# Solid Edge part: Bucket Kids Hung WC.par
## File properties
Title: Bucket Kids Hung WC
Author: DESYS
Template: Parte SCARABEO.par
Last saved by: i.fialdini
Revision: 55
Application: Solid Edge
Stile della faccia: Model Default
Coef. of Thermal Exp: 0.0
Thermal Conductivity: 0.0
Specific Heat: 0.0
Modulus of Elasticity: 0.0
Poisson's Ratio: 0.0
Yield Stress: 0.0
Ultimate Stress: 0.0
Elongation: 0.0
Tipo di contenuto documento: 0
Precisione: 0.990
Document Number: 8815
Revision: 0
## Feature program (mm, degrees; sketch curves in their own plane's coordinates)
lofted protrusion "unnamed LoftedProtrusion 1"
sketch for "unnamed Protrusion 1" plane through (-217.5, 0, -220) normal (-1, 0, 0) x-axis (0, -1, 0)
extrude "unnamed Protrusion 1" add through along -normal
fillet "unnamed Round 1"
fillet "Rotondo_24" radius 200
sketch for "ScavoEstrusione_3" plane through (-17.4962, 0.1233, 0) normal (0, 0, 1) x-axis (0, -1, 0)
extrude "ScavoEstrusione_3" cut finite 135 along -normal
sketch for "unnamed Cutout 1" #1 plane through (0, 0, -135) normal (0, 0, 1) x-axis (-1, 0, 0)
  arc centre (-16.5, 0) radius 100 from (-16.5, -100) to (-16.5, 100) ccw
  line (-16.5, 100) -> (-46.5, 100)
  arc centre (-46.5, 0) radius 100 from (-46.5, 100) to (-46.5, -100) ccw
  line (-46.5, -100) -> (-16.5, -100)
sketch for "unnamed Cutout 1" #2 plane through (0, 0, -135) normal (0, 0, 1) x-axis (-1, 0, 0)
  arc centre (-16.5, 0) radius 115 from (-16.5, -115) to (-16.5, 115) ccw
  line (-16.5, 115) -> (-46.5, 115)
  arc centre (-46.5, 0) radius 115 from (-46.5, 115) to (-46.5, -115) ccw
  line (-46.5, -115) -> (-16.5, -115)
extrude "unnamed Cutout 1" cut finite 70 along +normal
sketch for "unnamed Cutout 2" #1 plane through (20.5, 0, -65) normal (0, 0, 1) x-axis (1, 0, 0)
  arc centre (-4, 0) radius 115 from (-4, 115) to (-4, -115) ccw
  line (-4, -115) -> (26, -115)
  arc centre (26, 0) radius 115 from (26, -115) to (26, 115) ccw
  line (26, 115) -> (-4, 115)
sketch for "unnamed Cutout 2" #2 plane through (20.5, 0, -65) normal (0, 0, 1) x-axis (1, 0, 0)
  arc centre (-4, 0) radius 105 from (-4, 105) to (-4, -105) ccw
  line (-4, -105) -> (26, -105)
  arc centre (26, 0) radius 105 from (26, -105) to (26, 105) ccw
  line (26, 105) -> (-4, 105)
extrude "unnamed Cutout 2" cut finite 50 along +normal
sketch used by "ScavoEstrusione_6" plane through (-36.4973, -0.0393, -225) normal (0, 0, -1) x-axis (0, 1, 0)
extrude "ScavoEstrusione_6" cut finite 87 along -normal
sketch used by "ProtrusioneEstrusa_9" plane through (-36.4973, -0.0393, -225) normal (0, 0, -1) x-axis (-1, 0, 0)
  line (-158.0515, 10.8084) -> (-169.1638, 20.0393)
  line (-158.0515, -10.7298) -> (-169.1638, -19.9607)
extrude "ProtrusioneEstrusa_9" add through along -normal  Treatment1_DraftAngle = 3.5 deg
sketch for "unnamed Cutout 3" plane through (-36.4973, -0.0393, -225) normal (0, 0, -1) x-axis (1, 0, 0)
extrude "unnamed Cutout 3" cut to key point along -normal
sketch for "ScavoEstrusione_8" plane through (-36.4973, -0.0393, -225) normal (0, 0, -1) x-axis (1, 0, 0)
extrude "ScavoEstrusione_8" cut finite 261.6824 symmetric
mirror "unnamed Mirror 1" of "ScavoEstrusione_8" about plane through (0, 0, 0) normal (0, -1, 0)
extrude "unnamed Cutout 4" cut finite 261.6824 symmetric
sketch for "ProtrusioneEstrusa_10" plane through (-217.5, 0, -110) normal (-1, 0, 0) x-axis (0, 1, 0)
  line (-90.5, 115) -> (90.5, 115)
extrude "ProtrusioneEstrusa_10" add finite 40 along -normal
sketch for "unnamed RevolvedProtrusion 1" plane through (0, 0, 0) normal (1, 0, 0) x-axis (0, 1, 0)
  arc centre (0, -40.7154) radius 146.8479 from (-110, -138) to (0, -187.5633) ccw
revolve "unnamed RevolvedProtrusion 1" add full turn 360 deg about sketch line (0, 0) -> (0, -253.8574)
sketch for "ScavoEstrusione_10" plane through (-217.5, 0, -140) normal (-1, 0, 0) x-axis (0, 1, 0)
extrude "ScavoEstrusione_10" cut finite 80 along -normal
fillet "Rotondo_34" radius 25
fillet "Rotondo_35" radius 25
fillet "Rotondo_36" radius 10
fillet "Rotondo_37" radius 5
fillet "Rotondo_38" radius 1
fillet "Rotondo_40" radius 1
fillet "Rotondo_41" radius 2
fillet "Rotondo_42" radius 4
fillet "Rotondo_44" radius 10
fillet "Rotondo_46" radius 1
fillet "Rotondo_47" radius 5  Radii2 = 4 mm
delete blends "unnamed DeleteBlends 1"
delete faces "unnamed DeleteFaces 1"
sketch for "ScavoRivoluzione_1" plane through (0, 0, 0) normal (0, -1, 0) x-axis (1, 0, 0)
  line (-178.5, -138) -> (-110, -138)
  arc centre (0, -40.7154) radius 146.8479 from (-121.6287, -123) to (-110, -138) ccw
  line (-121.6287, -123) -> (-217.5, -123)
revolve "ScavoRivoluzione_1" cut finite 29 deg about sketch line (0, -40.7154) -> (0, -174.5688)
replace surface "unnamed ReplaceSurface 1"
replace surface "unnamed ReplaceSurface 2"
sketch for "ProtrusioneEstrusa_11" plane through (-24.0203, 0, -138) normal (0, 0, -1) x-axis (0, 1, 0)
extrude "ProtrusioneEstrusa_11" add finite 150 along +normal  Treatment1_DraftAngle = 2.5 deg
draft "unnamed Draft 1"
fillet "Rotondo_29" radius 58.5
sketch for "ProtrusioneEstrusa_12" plane through (-183.5, 0, -140) normal (-1, 0, 0) x-axis (0, 1, 0)
  circle centre (0, 45) radius 47
extrude "ProtrusioneEstrusa_12" add through along -normal  Treatment1_DraftAngle = 3 deg
sketch for "ScavoEstrusione_12" plane through (0, 0, 0) normal (0, -1, 0) x-axis (1, 0, 0)
  line (-140.2746, -217.0534) -> (-129.0341, -190.5)
  line (-129.0341, -190.5) -> (-73.4248, -190.5)
  line (-73.4248, -190.5) -> (-72.2654, -217.0534)
  line (-72.2654, -217.0534) -> (-140.2746, -217.0534)
extrude "ScavoEstrusione_12" cut finite 139.0806 symmetric
sketch for "unnamed Cutout 5" #1 plane through (-217.5, 0, -140) normal (-1, 0, 0) x-axis (0, -1, 0)
  circle centre (-91, 60) radius 14
  dimension (linear) = 91
  dimension (linear) = 91
sketch for "unnamed Cutout 5" #2 plane through (-217.5, 0, -140) normal (-1, 0, 0) x-axis (0, -1, 0)
  circle centre (91, 60) radius 14
extrude "unnamed Cutout 5" cut finite 40 along -normal
sketch for "ScavoEstrusione_14" #1 plane through (-217.5, 0, -140) normal (-1, 0, 0) x-axis (0, -1, 0)
  circle centre (-47.5, 126) radius 4
sketch for "ScavoEstrusione_14" #2 plane through (-217.5, 0, -140) normal (-1, 0, 0) x-axis (0, -1, 0)
  circle centre (-100.5, 126) radius 5
sketch for "ScavoEstrusione_14" #3 plane through (-217.5, 0, -140) normal (-1, 0, 0) x-axis (0, -1, 0)
  circle centre (100.5, 126) radius 5
sketch for "ScavoEstrusione_14" #4 plane through (-217.5, 0, -140) normal (-1, 0, 0) x-axis (0, -1, 0)
  circle centre (47.5, 126) radius 4
extrude "ScavoEstrusione_14" cut finite 75.5672 along -normal
sketch for "unnamed Cutout 6" plane through (-217.5, 0, -140) normal (-1, 0, 0) x-axis (0, -1, 0)
  circle centre (0, 95) radius 24
extrude "unnamed Cutout 6" cut through along -normal
sketch for "ScavoEstrusione_16" plane through (-217.5, 0, -140) normal (-1, 0, 0) x-axis (0, -1, 0)
  circle centre (0, 95) radius 27.5
extrude "ScavoEstrusione_16" cut finite 38 along -normal
sketch for "ScavoEstrusione_17" plane through (-217.5, 0, -140) normal (-1, 0, 0) x-axis (0, -1, 0)
  line (-107.5, 78.7816) -> (-107.5, 113.3583)
  line (-107.5, 41.2184) -> (-107.5, -52)
  line (-107.5, -52) -> (-95.5683, -52)
  arc centre (0, -40.7748) radius 96.2252 from (-95.5683, -52) to (95.5683, -52) ccw
  line (107.5, -52) -> (95.5683, -52)
  line (107.5, 41.2184) -> (107.5, -52)
  arc centre (91, 60) radius 25 from (107.5, 78.7816) to (107.5, 41.2184) ccw
  line (107.5, 78.7816) -> (107.5, 118.2601)
  arc centre (99.6624, 131.0496) radius 15 from (84.8031, 129) to (107.5, 118.2601) ccw
  line (62.1969, 129) -> (84.8031, 129)
  arc centre (47.5, 126) radius 15 from (34.1398, 119.1805) to (62.1969, 129) ccw
  arc centre (25.233, 114.6342) radius 10 from (34.1398, 119.1805) to (29.302, 123.7689) ccw
  arc centre (0, 57.9871) radius 72.0129 from (-29.302, 123.7689) to (29.302, 123.7689) cw
  arc centre (-25.233, 114.6342) radius 10 from (-29.302, 123.7689) to (-34.1398, 119.1805) ccw
  line (-84.8031, 129) -> (-62.1969, 129)
extrude "ScavoEstrusione_17" cut finite 4 along -normal
sketch for "unnamed Cutout 7" plane through (-13.6958, 0, -260.9151) normal (0, 0, 1) x-axis (1, 0, 0)
  line (-53.8042, 10.982) -> (-53.8042, 38.9877)
  line (-53.8042, 38.9877) -> (-65.552, 38.9877)
  arc centre (-32.7479, 0) radius 50.9524 from (-65.552, 38.9877) to (-77.925, 23.5624) ccw
  line (-53.8042, 10.982) -> (-77.925, 23.5624)
extrude "unnamed Cutout 7" cut to key point along +normal
extrude "unnamed Cutout 8" cut finite 68.9151
sketch for "ProtrusioneEstrusa_15" plane through (-67.5, 0, -163.5) normal (1, 0, 0) x-axis (0, 1, 0)
  line (-36.0423, -43.5) -> (35.0423, -43.5)
  line (35.0423, -43.5) -> (36.0423, -43.5)
  line (36.0423, -43.5) -> (36.0423, -28.4999)
  arc centre (0, -28.5) radius 36.0423 from (36.0423, -28.4999) to (-36.0423, -28.5) ccw
  line (-36.0423, -28.5) -> (-36.0423, -43.5)
extrude "ProtrusioneEstrusa_15" add finite 2 along -normal
sketch for "ScavoEstrusione_31" plane through (-36.4973, -0.0393, -236.1368) normal (0, 0, -1) x-axis (-1, 0, 0)
extrude "ScavoEstrusione_31" cut finite 27.8207 along -normal
replace surface "unnamed ReplaceSurface 3"
fillet "Rotondo_31" radius 10
draft "Spoglia_9"  Angles1 = 20 deg
replace surface "unnamed ReplaceSurface 4"
fillet "Rotondo_32" radius 5
sketch for "unnamed Cutout 9" plane through (20.5, 0, -135) normal (0, 0, 1) x-axis (1, 0, 0)
  line (-67, 50) -> (-2, 50)
  arc centre (-2, 0) radius 50 from (-2, 50) to (-2, -50) cw
  line (-2, -50) -> (-67, -50)
  arc centre (-67, -35) radius 15 from (-82, -35) to (-67, -50) ccw
  line (-82, -35) -> (-82, 35)
  arc centre (-67, 35) radius 15 from (-67, 50) to (-82, 35) ccw
  dimension (linear) = 82
extrude "unnamed Cutout 9" cut finite 50 along -normal
multibody boolean "unnamed MultibodyBoolean 1"
draft "Spoglia_10"  Angles1 = 20 deg
sketch for "ProtrusioneEstrusa_16" plane through (-183.5, 0, -192) normal (-1, 0, 0) x-axis (0, 0, 1)
extrude "ProtrusioneEstrusa_16" add finite 12 along -normal
sketch for "unnamed Cutout 10" plane through (-100.9034, 86.9531, -138) normal (0, 0, -1) x-axis (0, -1, 0)
extrude "unnamed Cutout 10" cut finite 80 along -normal
mirror "unnamed Mirror 2" of "unnamed Cutout 10" about plane through (0, 0, 0) normal (0, -1, 0)
extrude "unnamed Cutout 11" cut finite 80
multibody boolean "unnamed MultibodyBoolean 2"
fillet "Rotondo_49" radius 55
fillet "Rotondo_52" radius 15
fillet "Rotondo_51" radius 150
fillet "Rotondo_53" radius 5
fillet "Rotondo_54" radius 10
Other named dimensions: "Estendi_superficie_2": Distance = 97.2568 mm | "Estendi_superficie_3": Distance = 86.6935 mm | "Estendi_superficie_4": Distance = 99 mm | "SuperficieEstrusa_2": FiniteDepth = 122.2754 mm | "SuperficieOffset_2": Distance = 2 mm | "SuperficieOffset_3": Distance = 5 mm | "Estendi_superficie_8": Distance = 63.1496 mm | "SuperficieOffset_4": Distance = 5 mm | "Spostamento_faccia_5": Distance = 46.6269 mm | "SuperficieOffset_5": Distance = 20 mm | "Spostamento_faccia_7": Distance = 8 mm
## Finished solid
Body 1: solid body, 29 faces, 68 edges, 42 vertices.
  Faces by surface: plane 10, cylinder 7, spline 4, cone 3, torus 3, blend 1, sphere 1
  Edges by curve: line 21, intersection 19, circle 18, spline 6, curve on surface 3, ellipse 1
Body 2: sheet body, 1 face, 6 edges, 6 vertices.
  Faces by surface: torus 1
  Edges by curve: circle 5, curve on surface 1
Body 3: sheet body, 1 face, 6 edges, 6 vertices.
  Faces by surface: torus 1
  Edges by curve: circle 5, intersection 1
Body 4: sheet body, 3 faces, 10 edges, 8 vertices.
  Faces by surface: cylinder 2, swept 1
  Edges by curve: circle 4, line 4, spline 2
Body 5: sheet body, 2 faces, 10 edges, 8 vertices.
  Faces by surface: cone 1, torus 1
  Edges by curve: circle 5, intersection 3, line 2
Body 6: sheet body, 1 face, 4 edges, 4 vertices.
  Faces by surface: cone 1
  Edges by curve: line 2, circle 1, intersection 1
Body 7: sheet body, 1 face, 6 edges, 6 vertices.
  Faces by surface: plane 1
  Edges by curve: line 6
Body 8: sheet body, 1 face, 6 edges, 6 vertices.
  Faces by surface: plane 1
  Edges by curve: line 6
Body 9: sheet body, 1 face, 8 edges, 8 vertices.
  Faces by surface: sphere 1
  Edges by curve: curve on surface 6, intersection 2
Body 10: solid body, 337 faces, 771 edges, 437 vertices.
  Faces by surface: cylinder 97, plane 86, torus 72, blend 54, cone 10, spline 9, sphere 7, swept 2
  Edges by curve: circle 328, line 254, intersection 151, curve on surface 17, ellipse 15, spline 6
Bounding box of the edges (mm; curved faces can reach further): 433.628 x 291.341 x 288.000, from (-246.3014, -145.6735, -288) to (187.3271, 145.6677, 0).
Cylindrical faces by radius (mm): R1 x28, R2 x6, R4 x8, R5 x10, R6 x3, R10 x10, R14 x2, R15 x4, R20 x4, R24 x1, R25 x6, R27.5 x1, R33.5 x2, R35.9784 x1, R53.5 x2, R55 x4, R66.2212 x2, R72.0129 x1, R86.2521 x1, R96.2252 x1, R98.2521 x1, R100 x2, R105 x2, R110 x2, R115 x2
Conical faces (half-angle, radius in mm at the cone's reference point): 3 deg R42.0069 x2, 3 deg R47 x1, 3.5 deg R14 x1, 5 deg R56.5682 x4, 5 deg R61.5491 x4, 20 deg R15 x2, 20 deg R50 x1
Toroidal faces (ring radius, tube radius in mm): R1 r1 x20, R4 r1 x2, R7.9438 r33.5 x2, R7.9438 r53.5 x2, R7.9438 r56.5 x1, R7.9438 r58.5 x2, R9 r5 x2, R11 r1 x2, R11.8508 r55 x2, R13.0593 r1 x1, R14 r1 x4, R15 r1 x2, R24 r1 x2, R25 r1 x1, R26.5 r1 x1, R28.5 r1 x1, R36.9784 r1 x1, R46.051 r1 x1, R67.5052 r25 x1, R73.0129 r1 x1, R77.6839 r10 x1, R77.6839 r15 x2, R87.2521 r1 x1, R88.2521 r2 x1, R90 r25 x2, R97.2252 r1 x1, R100 r10 x2, R110 r10 x2, R111 r1 x2, R114.4171 r10 x4, R122.8617 r10 x2, R126.3999 r10 x2, R126.8259 r10 x1, R149.3201 r10 x2, R155.7125 r10 x2
Spherical faces by radius (mm): R4 x2, R10 x4, R38.755 x1, R146.8479 x2
Planar faces by outward normal: +x 5, +y 12, +z 12, -x 11, -y 12, -z 26, oblique 18
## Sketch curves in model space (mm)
line (-67.5, 35, -192) -> (-67.5, -35, -192)
line (-67.5, 35, -192) -> (-67.5, -35, -192)
arc centre (-46.4438, 0, -192) radius 55.0861 from (-88.9817, -35, -192) through (-101.5052, 1.6487, -192) to (-88.9817, 35, -192)
line (-67.5, 35, -192) -> (-88.9817, 35, -192)
arc centre (-11.0383, 0, -192) radius 85.4411 from (-88.9817, -35, -192) through (-96.4794, 0, -192) to (-88.9817, 35, -192)
line (-67.5, -35, -192) -> (-88.9817, -35, -192)
line (-217.5, 107.5, -192) -> (-217.5, 95.5683, -192)
arc centre (-217.5, 0, -180.7748) radius 96.2252 from (-217.5, 95.5683, -192) through (-217.5, -5.7068, -276.8306) to (-217.5, -95.5683, -192)
line (-217.5, -107.5, -192) -> (-217.5, -95.5683, -192)
line (-217.5, -107.5, -98.7816) -> (-217.5, -107.5, -192)
arc centre (-217.5, -91, -80) radius 25 from (-217.5, -107.5, -61.2184) through (-217.5, -66.0996, -82.2291) to (-217.5, -107.5, -98.7816)
line (-217.5, -107.5, -61.2184) -> (-217.5, -107.5, -21.7399)
arc centre (-217.5, -99.6624, -8.9504) radius 15 from (-217.5, -84.8031, -11) through (-217.5, -93.2466, -22.5091) to (-217.5, -107.5, -21.7399)
line (-217.5, -62.1969, -11) -> (-217.5, -84.8031, -11)
arc centre (-217.5, -47.5, -14) radius 15 from (-217.5, -34.1398, -20.8195) through (-217.5, -52.455, -28.158) to (-217.5, -62.1969, -11)
arc centre (-217.5, -25.233, -25.3658) radius 10 from (-217.5, -34.1398, -20.8195) through (-217.5, -32.1146, -18.1102) to (-217.5, -29.302, -16.2311)
arc centre (-217.5, 0, -82.0129) radius 72.0129 from (-217.5, 29.302, -16.2311) through (-217.5, 0, -10) to (-217.5, -29.302, -16.2311)
arc centre (-217.5, 25.233, -25.3658) radius 10 from (-217.5, 29.302, -16.2311) through (-217.5, 32.1146, -18.1102) to (-217.5, 34.1398, -20.8195)
arc centre (-217.5, 47.5, -14) radius 15 from (-217.5, 34.1398, -20.8195) through (-217.5, 52.455, -28.158) to (-217.5, 62.1969, -11)
line (-217.5, 84.8031, -11) -> (-217.5, 62.1969, -11)
arc centre (-217.5, 99.5109, -13.9463) radius 15 from (-217.5, 84.8031, -11) through (-217.5, 91.3718, -26.5461) to (-217.5, 107.5, -26.6417)
line (-217.5, 107.5, -61.2184) -> (-217.5, 107.5, -26.6417)
arc centre (-217.5, 91, -80) radius 25 from (-217.5, 107.5, -61.2184) through (-217.5, 66.0996, -82.2291) to (-217.5, 107.5, -98.7816)
line (-217.5, 107.5, -98.7816) -> (-217.5, 107.5, -192)
arc centre (-217.5, 0, -186.7479) radius 98.2521 from (-217.5, 92.0954, -220.981) through (-217.5, -2.911, -284.9569) to (-217.5, -92.0954, -220.981)
line (-217.5, -79.1594, -221) -> (-217.5, -81.1594, -221)
line (-217.5, -81.1594, -221) -> (-217.5, -81.1594, -201)
line (-217.5, -81.1594, -201) -> (-217.5, -76.9883, -201)
line (-217.5, -76.9883, -201) -> (-217.5, -76.9883, -173)
line (-217.5, -76.9883, -173) -> (-217.5, -73.9883, -173)
line (-217.5, -73.9883, -173) -> (-217.5, -57.5, -123)
line (-217.5, -57.5, -123) -> (-217.5, 57.5, -123)
line (-217.5, 73.9883, -173) -> (-217.5, 57.5, -123)
line (-217.5, 76.9883, -173) -> (-217.5, 73.9883, -173)
line (-217.5, 76.9883, -201) -> (-217.5, 76.9883, -173)
line (-217.5, 81.1594, -201) -> (-217.5, 76.9883, -201)
line (-217.5, 81.1594, -221) -> (-217.5, 81.1594, -201)
line (-217.5, 79.1594, -221) -> (-217.5, 81.1594, -221)
arc centre (-217.5, 0, -186.7479) radius 86.2521 from (-217.5, 79.1594, -221) through (-217.5, -2.5704, -272.9617) to (-217.5, -79.1594, -221)
line (188.5, 0, -225) -> (-217.5, 0, -225)
circle centre (24.5, 0, -225) radius 120
line (16.5, -100, -135) -> (46.5, -100, -135)
arc centre (46.5, 0, -135) radius 100 from (46.5, -100, -135) through (146.4561, 2.9633, -135) to (46.5, 100, -135)
line (46.5, 100, -135) -> (16.5, 100, -135)
arc centre (16.5, 0, -135) radius 100 from (16.5, 100, -135) through (-83.4561, -2.9633, -135) to (16.5, -100, -135)
line (46.5, 115, -135) -> (16.5, 115, -135)
arc centre (16.5, 0, -135) radius 115 from (16.5, 115, -135) through (-98.4495, -3.4078, -135) to (16.5, -115, -135)
line (16.5, -115, -135) -> (46.5, -115, -135)
arc centre (46.5, 0, -135) radius 115 from (46.5, -115, -135) through (161.4495, 3.4078, -135) to (46.5, 115, -135)
circle centre (24.5, 0, 0) radius 120
arc centre (42.5, 0, 0) radius 146 from (42.5, -146, 0) through (188.4359, 4.3265, 0) to (42.5, 146, 0)
line (42.5, 146, 0) -> (-42.5, 146, 0)
arc centre (-42.5, 0, 0) radius 146 from (-42.5, 146, 0) through (-188.4359, -4.3265, 0) to (-42.5, -146, 0)
line (-42.5, -146, 0) -> (42.5, -146, 0)
arc centre (22.4612, 0, -40.4457) radius 12.999 from (22.4612, 12.999, -40.4457) through (35.4545, -0.3852, -40.4457) to (22.4612, -12.999, -40.4457)
line (22.4612, 12.999, -40.4457) -> (8.2958, 12.999, -40.4457)
line (8.2958, 12.999, -40.4457) -> (8.2958, -12.999, -40.4457)
line (8.2958, -12.999, -40.4457) -> (22.4612, -12.999, -40.4457)
spline (-24.6268, 107.5, -225) -> (-5.2279, 108.0306, -225) -> (14.006, 109.4983, -225)
arc centre (24.5, 0, -225) radius 110 from (14.006, 109.4983, -225) through (31.0156, 109.8069, -225) to (47.8694, 107.4889, -225)
arc centre (24.5, 0, -225) radius 110 from (47.8694, 107.4889, -225) through (134.494, 1.1447, -225) to (56.453, -105.2569, -225)
arc centre (24.5, 0, -225) radius 110 from (56.453, -105.2569, -225) through (35.6276, -109.4357, -225) to (14.3873, -109.5342, -225)
spline (14.3873, -109.5342, -225) -> (-5.7445, -108.0432, -225) -> (-26.0499, -107.5, -225)
line (-26.0499, -107.5, -225) -> (-178.5, -107.5, -225)
line (-178.5, -107.5, -225) -> (-178.5, 107.5, -225)
line (-178.5, 107.5, -225) -> (-24.6268, 107.5, -225)
line (-217.5, 118.5, 0) -> (-217.5, 118.5, -225)
line (-217.5, 118.5, -225) -> (-217.5, -118.5, -225)
line (-217.5, -118.5, -225) -> (-217.5, -118.5, 0)
line (-217.5, -118.5, 0) -> (-217.5, 118.5, 0)
arc centre (11.5, 0, -138) radius 55 from (11.5, -55, -138) through (66.4758, 1.6298, -138) to (11.5, 55, -138)
line (11.5, -55, -138) -> (-38.5, -55, -138)
arc centre (-38.5, 0, -138) radius 55 from (-38.5, 55, -138) through (-93.4758, -1.6298, -138) to (-38.5, -55, -138)
line (-38.5, 55, -138) -> (11.5, 55, -138)
line (121.5542, -10.7691, -225) -> (132.6665, -20, -225)
arc centre (130.5, 0, -225) radius 14 from (121.5542, 10.7691, -225) through (116.5, 0, -225) to (121.5542, -10.7691, -225)
line (121.5542, 10.7691, -225) -> (132.6665, 20, -225)
circle centre (-183.5, 0, -185) radius 47
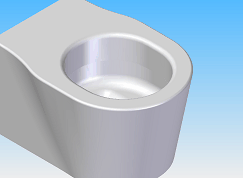
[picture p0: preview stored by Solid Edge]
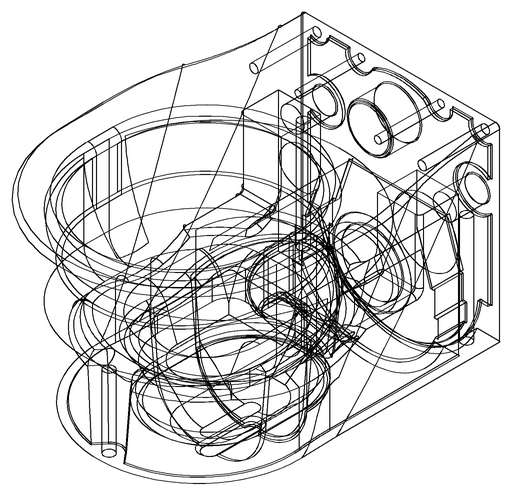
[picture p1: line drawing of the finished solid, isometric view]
